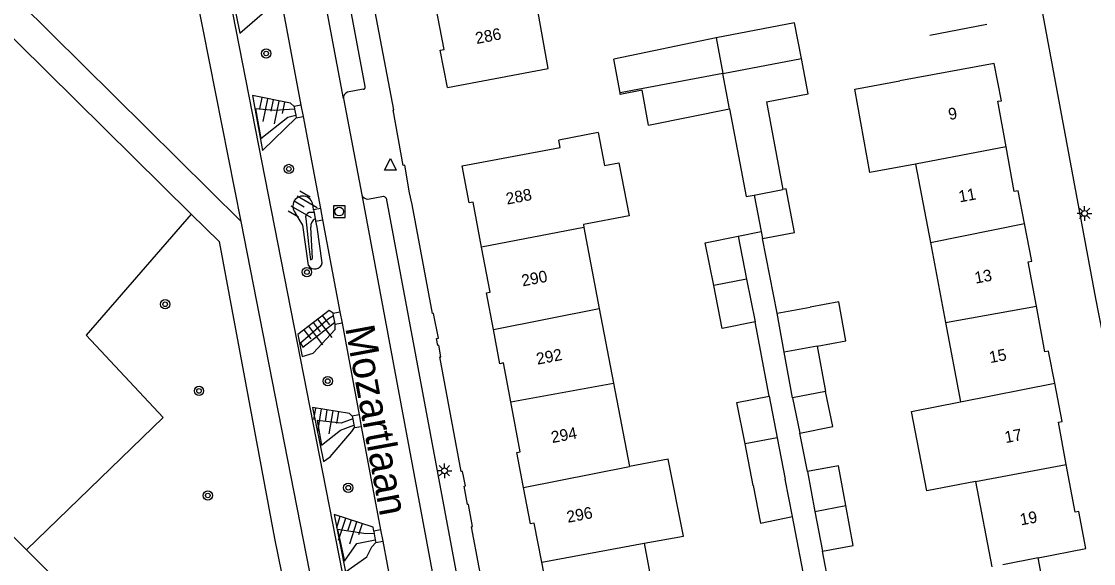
# Model space of a CAD drawing. Extents: x 132999 to 136000, y 398499 to 400501.
# Drawn here: x 133335 to 133427, y 398911.3 to 398957.8 of the extents above; entities that cross this region are included whole.
import ezdxf

# ---------------------------------------------------------------- set-up
doc = ezdxf.new("R2010")
doc.units = 0
for name, color, linetype in [('gg-afsc-erfafscheiding', 7, 'Continuous'), ('gg-afsc-hekwerk', 7, 'Continuous'), ('gg-afsc-muur', 7, 'Continuous'), ('gg-anno-huisnummerreeks BGT', 7, 'Continuous'), ('gg-anno-openbare ruimte label', 7, 'Continuous'), ('gg-bbg-bijgebouw', 7, 'Continuous'), ('gg-bbg-gedigitaliseerde bebouwing', 7, 'Continuous'), ('gg-bbg-gedigitaliseerde bijgebouw', 7, 'Continuous'), ('gg-bbg-hoofdgebouw', 7, 'Continuous'), ('gg-bbg-luifel en loopbrug', 7, 'Continuous'), ('gg-bbg-tussenscheiding', 7, 'Continuous'), ('gg-knt-bovenkant onderkant talud', 7, 'Continuous'), ('gg-knt-verharding', 7, 'Continuous'), ('gg-knt-verharding nz', 7, 'Continuous'), ('gt-grn-groengrens', 7, 'Continuous'), ('gt-symb-boom', 7, 'Continuous'), ('gt-symb-lichtmast', 7, 'Continuous'), ('gt-symb-rioolschacht', 7, 'Continuous'), ('gt-symb-talud symbool', 7, 'Continuous'), ('gt-symb-waterafsluiter', 7, 'Continuous')]:
    doc.layers.add(name, color=color, linetype=linetype)

# ---------------------------------------------------------------- blocks, each defined once
blk = doc.blocks.new('gt0-WAFSL')
at = {"layer": 'gt-symb-waterafsluiter'}
for p, q in [((-0.5, -0.333), (0, 0.667)), ((0, 0.667), (0.5, -0.333)), ((0.5, -0.333), (-0.5, -0.333))]:
    blk.add_line(p, q, dxfattribs=at)
blk = doc.blocks.new('gt0-TALUD_1')
at = {"layer": 'gt-symb-talud symbool'}
for p, q in [((-1, -1), (-1, 0)), ((-0.5, -2), (-0.5, 0)), ((0, -1), (0, 0)), ((0.5, -2), (0.5, 0)), ((1, -1), (1, 0))]:
    blk.add_line(p, q, dxfattribs=at)
blk = doc.blocks.new('gt0-BOOM')
at = {"layer": 'gt-symb-boom'}
for radius in [0.4, 0.2]:
    blk.add_circle((0, 0), radius, dxfattribs=at)
blk = doc.blocks.new('gt0-LMAST')
at = {"layer": 'gt-symb-lichtmast'}
for p, q in [((-0.182, 0.173), (-0.447, 0.438)), ((-0.005, 0.246), (-0.005, 0.621)), ((0.172, 0.173), (0.437, 0.438)), ((-0.255, -0.004), (-0.63, -0.004)), ((-0.182, -0.181), (-0.447, -0.446)), ((-0.005, -0.254), (-0.005, -0.629)), ((0.437, -0.446), (0.172, -0.181)), ((0.245, -0.004), (0.62, -0.004))]:
    blk.add_line(p, q, dxfattribs=at)
blk.add_circle((-0.005, -0.004), 0.25, dxfattribs=at)
blk = doc.blocks.new('gt0-RS')
at = {"layer": 'gt-symb-rioolschacht'}
blk.add_lwpolyline([(-0.5, -0.5), (0.5, -0.5), (0.5, 0.5), (-0.5, 0.5)], close=True, dxfattribs=at)
blk.add_circle((0, 0), 0.375, dxfattribs=at)

msp = doc.modelspace()

# ---------------------------------------------------------------- linework, layer by layer
at = {"layer": 'gg-afsc-erfafscheiding'}
for p, q in [((133396.506, 398939.394), (133398.476, 398939.786)), ((133399.86, 398932.801), (133398.591, 398939.185)), ((133399.171, 398925.662), (133397.972, 398932.036)), ((133402.473, 398919.203), (133401.804, 398922.492)), ((133402.409, 398908.948), (133401.17, 398915.344)), ((133404.553, 398908.312), (133403.743, 398912.387))]:
    msp.add_line(p, q, dxfattribs=at)
at = {"layer": 'gg-afsc-hekwerk'}
msp.add_line((133368.467, 398880.359), (133351.55, 398966.66), dxfattribs=at)
at = {"layer": 'gg-afsc-muur'}
msp.add_line((133417.869, 398957.553), (133412.961, 398956.596), dxfattribs=at)
at = {"layer": 'gg-bbg-bijgebouw'}
for p, q in [((133386.375, 398951.675), (133385.828, 398954.576)), ((133423.41, 398905.91), (133422.26, 398911.81))]:
    msp.add_line(p, q, dxfattribs=at)
msp.add_lwpolyline([(133388.828, 398948.905), (133388.262, 398951.908), (133386.397, 398951.557), (133386.375, 398951.675)], dxfattribs=at)
at = {"layer": 'gg-bbg-gedigitaliseerde bebouwing'}
for p, q in [((133380.216, 398953.787), (133378.938, 398960.85)), ((133418.48, 398954.19), (133410.389, 398952.71)), ((133411.744, 398945.564), (133413.015, 398938.858)), ((133383.222, 398940.391), (133383.272, 398940.127)), ((133383.272, 398940.127), (133384.594, 398933.194)), ((133413.015, 398938.858), (133414.318, 398931.984)), ((133384.594, 398933.194), (133385.815, 398926.786)), ((133414.318, 398931.984), (133415.605, 398925.194)), ((133385.815, 398926.786), (133387.18, 398919.63)), ((133416.899, 398918.366), (133418.291, 398911.026)), ((133388.431, 398913.064), (133389.842, 398905.663))]:
    msp.add_line(p, q, dxfattribs=at)
for points in [[(133411.744, 398945.564), (133407.83, 398944.848), (133406.521, 398952.003), (133410.389, 398952.71)], [(133384.488, 398948.286), (133385.027, 398945.456), (133386.278, 398945.694), (133387.147, 398941.14), (133383.222, 398940.391)], [(133416.899, 398918.366), (133412.72, 398917.548), (133411.385, 398924.368), (133415.605, 398925.194)], [(133388.431, 398913.064), (133391.808, 398913.681), (133390.516, 398920.283), (133387.18, 398919.63)]]:
    msp.add_lwpolyline(points, dxfattribs=at)
at = {"layer": 'gg-bbg-gedigitaliseerde bijgebouw'}
for p, q in [((133394.628, 398956.397), (133385.828, 398954.576)), ((133398.959, 398950.913), (133400.336, 398943.385)), ((133388.828, 398948.905), (133395.784, 398950.31)), ((133397.879, 398942.916), (133398.476, 398939.786)), ((133398.476, 398939.786), (133398.591, 398939.185)), ((133396.506, 398939.394), (133397.239, 398935.715)), ((133397.239, 398935.715), (133397.972, 398932.036)), ((133399.86, 398932.801), (133402.699, 398933.319)), ((133400.47, 398929.456), (133399.86, 398932.801)), ((133403.309, 398929.974), (133404.023, 398926.062)), ((133401.183, 398925.544), (133400.47, 398929.456)), ((133404.023, 398926.062), (133401.183, 398925.544)), ((133399.171, 398925.662), (133399.866, 398922.113)), ((133399.866, 398922.113), (133400.561, 398918.564)), ((133397.804, 398918.024), (133397.109, 398921.573)), ((133401.17, 398915.344), (133400.561, 398918.564)), ((133402.473, 398919.203), (133403.108, 398915.795)), ((133403.108, 398915.795), (133403.743, 398912.387))]:
    msp.add_line(p, q, dxfattribs=at)
for points in [[(133401.938, 398954.634), (133401.36, 398957.677), (133394.628, 398956.397)], [(133398.959, 398950.913), (133402.517, 398951.589), (133401.938, 398954.634)], [(133395.784, 398950.31), (133397.213, 398942.79), (133397.879, 398942.916)], [(133398.591, 398939.185), (133401.348, 398939.711), (133400.636, 398943.442), (133400.336, 398943.385)], [(133394.417, 398935.153), (133393.684, 398938.832), (133396.506, 398939.394)], [(133397.972, 398932.036), (133395.149, 398931.474), (133394.417, 398935.153)], [(133403.309, 398929.974), (133405.771, 398930.424), (133405.16, 398933.769), (133402.699, 398933.319)], [(133397.109, 398921.573), (133396.414, 398925.122), (133399.171, 398925.662)], [(133405.753, 398916.287), (133405.118, 398919.696), (133402.473, 398919.203)], [(133397.804, 398918.024), (133398.437, 398914.793), (133401.17, 398915.344)], [(133403.743, 398912.387), (133406.388, 398912.88), (133405.753, 398916.287)]]:
    msp.add_lwpolyline(points, dxfattribs=at)
at = {"layer": 'gg-bbg-hoofdgebouw'}
for p, q in [((133371.56, 398952.15), (133380.216, 398953.787)), ((133384.488, 398948.286), (133381.12, 398947.63))]:
    msp.add_line(p, q, dxfattribs=at)
for points in [[(133371.56, 398952.15), (133370.94, 398955.34), (133371.26, 398955.4), (133370.517, 398959.241)], [(133419.527, 398947.049), (133418.82, 398950.96), (133419.13, 398951.01), (133418.48, 398954.19)], [(133374.485, 398938.448), (133373.75, 398942.3), (133373.43, 398942.24), (133372.83, 398945.42), (133381.23, 398947), (133381.12, 398947.63)], [(133421.1, 398940.47), (133420.54, 398943.28), (133420.22, 398943.22), (133419.527, 398947.049)], [(133422.117, 398933.406), (133421.42, 398937.2), (133421.74, 398937.26), (133421.1, 398940.47)], [(133375.502, 398931.382), (133374.9, 398934.54), (133375.22, 398934.6), (133374.485, 398938.448)], [(133423.689, 398926.776), (133423.15, 398929.53), (133422.84, 398929.47), (133422.117, 398933.406)], [(133377.001, 398925.178), (133376.37, 398928.52), (133376.06, 398928.46), (133375.502, 398931.382)], [(133424.686, 398919.817), (133424.01, 398923.44), (133424.33, 398923.5), (133423.689, 398926.776)], [(133378.086, 398917.85), (133377.5, 398920.83), (133377.81, 398920.89), (133377.001, 398925.178)], [(133422.26, 398911.81), (133426.36, 398912.62), (133425.77, 398915.77), (133425.45, 398915.72), (133424.686, 398919.817)], [(133379.656, 398911.429), (133379.01, 398914.79), (133378.7, 398914.73), (133378.086, 398917.85)], [(133384.83, 398904.68), (133380.75, 398903.88), (133380.16, 398907.08), (133380.48, 398907.14), (133379.656, 398911.429)]]:
    msp.add_lwpolyline(points, dxfattribs=at)
at = {"layer": 'gg-bbg-luifel en loopbrug'}
msp.add_line((133401.183, 398925.544), (133401.804, 398922.492), dxfattribs=at)
msp.add_lwpolyline([(133401.804, 398922.492), (133404.632, 398923.068), (133404.023, 398926.062)], dxfattribs=at)
at = {"layer": 'gg-bbg-tussenscheiding'}
for p, q in [((133394.628, 398956.397), (133395.206, 398953.354)), ((133395.206, 398953.354), (133401.938, 398954.634)), ((133395.206, 398953.354), (133386.375, 398951.675)), ((133395.784, 398950.31), (133395.206, 398953.354)), ((133419.527, 398947.049), (133411.744, 398945.564)), ((133397.879, 398942.916), (133400.336, 398943.385)), ((133383.272, 398940.127), (133374.485, 398938.448)), ((133413.015, 398938.858), (133421.1, 398940.47)), ((133397.239, 398935.715), (133394.417, 398935.153)), ((133375.502, 398931.382), (133384.594, 398933.194)), ((133414.318, 398931.984), (133422.117, 398933.406)), ((133403.309, 398929.974), (133400.47, 398929.456)), ((133377.001, 398925.178), (133385.815, 398926.786)), ((133415.605, 398925.194), (133423.689, 398926.776)), ((133399.866, 398922.113), (133397.109, 398921.573)), ((133378.086, 398917.85), (133387.18, 398919.63)), ((133416.899, 398918.366), (133424.686, 398919.817)), ((133403.108, 398915.795), (133405.753, 398916.287)), ((133379.656, 398911.429), (133388.431, 398913.064)), ((133422.26, 398911.81), (133419.241, 398911.214))]:
    msp.add_line(p, q, dxfattribs=at)
at = {"layer": 'gg-knt-bovenkant onderkant talud'}
for p, q in [((133360.065, 398941.667), (133360.015, 398941.932)), ((133360.112, 398941.417), (133359.671, 398941.412))]:
    msp.add_line(p, q, dxfattribs=at)
for points in [[(133356.529, 398960.361), (133356.488, 398960.655), (133352.773, 398961.473), (133353.723, 398956.813), (133356.714, 398959.378)], [(133358.39, 398950.522), (133358.093, 398950.787), (133354.81, 398951.451), (133355.667, 398946.754), (133358.576, 398949.539)], [(133358.436, 398950.278), (133356.715, 398950.16), (133355.071, 398950.313), (133355.53, 398947.782), (133357.841, 398949.605), (133358.534, 398949.762)], [(133359.622, 398936.876), (133359.14, 398940.33), (133358.519, 398941.361)], [(133359.395, 398940.904), (133359.616, 398938.749), (133359.803, 398937.365), (133359.974, 398937.476), (133359.82, 398940.176)], [(133360.804, 398937.095), (133360.383, 398940.176), (133360.251, 398940.684)], [(133361.736, 398932.8), (133361.415, 398933.03), (133358.711, 398930.965), (133359.091, 398929.063), (133360.041, 398929.349), (133361.917, 398931.405), (133361.921, 398931.818)], [(133361.778, 398932.574), (133361.355, 398932.31), (133358.947, 398930.214), (133359.149, 398929.881), (133360.403, 398930.842), (133361.882, 398932.023)], [(133363.388, 398923.957), (133363.135, 398924.181), (133359.971, 398924.705), (133360.91, 398920.079), (133361.499, 398920.465), (133363.336, 398922.633), (133363.571, 398922.974)], [(133363.428, 398923.742), (133362.431, 398923.361), (133360.357, 398923.593), (133360.73, 398921.484), (133362.383, 398922.764), (133363.531, 398923.187)], [(133365.227, 398914.102), (133365.185, 398914.454), (133361.837, 398915.539), (133362.801, 398910.617), (133364.625, 398911.883), (133365.076, 398912.752), (133365.411, 398913.119)], [(133365.271, 398913.865), (133364.372, 398913.884), (133362.125, 398914.233), (133362.728, 398911.537), (133363.783, 398913.027), (133365.364, 398913.367)]]:
    msp.add_lwpolyline(points, dxfattribs=at)
for centre, radius, start, end in [((133359.147, 398941.961), 0.868, 358.10964, 223.67252), ((133359.793, 398941.017), 0.414, 107.16902, 195.79989), ((133360.587, 398940.219), 0.769, 119.23844, 183.22626), ((133360.168, 398937.231), 0.651, 213.02758, 347.96579)]:
    msp.add_arc(centre, radius, start, end, dxfattribs=at)
at = {"layer": 'gg-knt-verharding'}
for p, q in [((133364.487, 398952.226), (133360.138, 398975.507)), ((133357.304, 398959.49), (133358.979, 398950.633)), ((133364.329, 398951.993), (133362.986, 398951.73)), ((133362.631, 398951.207), (133364.206, 398942.927)), ((133358.979, 398950.633), (133358.39, 398950.522)), ((133358.39, 398950.522), (133358.436, 398950.278)), ((133358.436, 398950.278), (133358.534, 398949.762)), ((133358.534, 398949.762), (133358.576, 398949.539)), ((133358.979, 398950.633), (133359.165, 398949.651)), ((133358.576, 398949.539), (133359.165, 398949.651)), ((133359.165, 398949.651), (133360.655, 398941.778)), ((133360.655, 398941.778), (133360.065, 398941.667)), ((133360.065, 398941.667), (133360.112, 398941.417)), ((133360.655, 398941.778), (133360.84, 398940.795)), ((133360.112, 398941.417), (133360.212, 398940.89)), ((133360.212, 398940.89), (133360.251, 398940.684)), ((133360.251, 398940.684), (133360.84, 398940.795)), ((133360.84, 398940.795), (133362.325, 398932.911)), ((133361.736, 398932.8), (133362.325, 398932.911)), ((133361.778, 398932.574), (133361.736, 398932.8)), ((133361.882, 398932.023), (133361.778, 398932.574)), ((133362.325, 398932.911), (133362.511, 398931.929)), ((133361.921, 398931.818), (133361.882, 398932.023)), ((133362.511, 398931.929), (133361.921, 398931.818)), ((133362.511, 398931.929), (133363.978, 398924.068)), ((133363.978, 398924.068), (133363.388, 398923.957)), ((133363.388, 398923.957), (133363.428, 398923.742)), ((133363.978, 398924.068), (133364.161, 398923.084)), ((133363.428, 398923.742), (133363.531, 398923.187)), ((133363.531, 398923.187), (133363.571, 398922.974)), ((133363.571, 398922.974), (133364.161, 398923.084)), ((133364.161, 398923.084), (133365.817, 398914.212)), ((133365.817, 398914.212), (133365.227, 398914.102)), ((133365.227, 398914.102), (133365.271, 398913.865)), ((133365.271, 398913.865), (133365.364, 398913.367)), ((133365.817, 398914.212), (133366.001, 398913.229)), ((133365.364, 398913.367), (133365.411, 398913.119)), ((133365.411, 398913.119), (133366.001, 398913.229)), ((133366.001, 398913.229), (133367.652, 398904.383))]:
    msp.add_line(p, q, dxfattribs=at)
for points in [[(133420.919, 398967.55), (133422.677, 398958.356), (133427.204, 398934.047), (133428.999, 398924.875), (133429.846, 398920.45)], [(133376.91, 398897.02), (133373.625, 398914.476), (133373.702, 398914.498), (133373.355, 398916.391), (133373.271, 398916.386), (133372.983, 398917.965), (133373.101, 398917.986), (133372.862, 398919.228), (133372.746, 398919.214), (133370.907, 398929.039), (133371, 398929.055), (133370.817, 398930.043), (133370.719, 398930.029), (133370.614, 398930.612), (133370.783, 398930.658), (133370.371, 398932.775), (133370.281, 398932.76), (133368.523, 398942.118), (133368.297, 398943.107), (133367.883, 398945.475), (133367.764, 398945.459), (133366.883, 398950.223), (133366.946, 398950.238), (133364.536, 398962.859)], [(133364.734, 398942.582), (133366.053, 398942.828), (133366.186, 398942.768), (133366.285, 398942.656), (133373.853, 398902.293)]]:
    msp.add_lwpolyline(points, dxfattribs=at)
for centre, radius, start, end in [((133363.092, 398951.276), 0.466, 103.12938, 188.53516), ((133364.32, 398952.169), 0.177, 273.04752, 18.66918), ((133364.714, 398943.128), 0.546, 201.56961, 272.10845)]:
    msp.add_arc(centre, radius, start, end, dxfattribs=at)
at = {"layer": 'gg-knt-verharding nz'}
for p, q in [((133362.631, 398951.207), (133358.037, 398975.789)), ((133364.206, 398942.927), (133372.004, 398901.291))]:
    msp.add_line(p, q, dxfattribs=at)
at = {"layer": 'gt-grn-groengrens'}
for p, q in [((133353.832, 398940.649), (133348.293, 398968.817)), ((133335.419, 398912.504), (133293.178, 398954.571))]:
    msp.add_line(p, q, dxfattribs=at)
for points in [[(133349.553, 398941.293), (133332.176, 398958.394), (133314.577, 398976.112)], [(133353.832, 398940.649), (133332.079, 398962.182), (133331.254, 398963.134)], [(133349.553, 398941.293), (133351.96, 398938.924), (133356.71, 398913.481), (133361.332, 398890.752), (133360.579, 398888.993), (133359.853, 398888.643), (133346.817, 398901.153), (133335.419, 398912.504)], [(133349.553, 398941.293), (133340.549, 398930.907), (133347.151, 398923.853), (133335.419, 398912.504)], [(133364.429, 398878.903), (133364.493, 398879.138), (133364.437, 398883.557), (133363.948, 398887.484), (133361.066, 398903.862), (133353.832, 398940.649)]]:
    msp.add_lwpolyline(points, dxfattribs=at)

# ---------------------------------------------------------------- block references
at = {"layer": 'gt-symb-boom'}
for p in [(133355.992, 398955.059), (133357.938, 398945.156), (133359.492, 398936.314), (133347.322, 398933.557), (133361.279, 398926.971), (133350.226, 398926.122), (133350.985, 398917.156)]:
    msp.add_blockref('gt0-BOOM', p, dxfattribs=at)
at = {"layer": 'gt-symb-boom', "rotation": -79.10581701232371}
msp.add_blockref('gt0-BOOM', (133363.041, 398917.82), dxfattribs=at)
at = {"layer": 'gt-symb-lichtmast'}
for p in [(133426.263, 398941.352), (133371.305, 398919.278)]:
    msp.add_blockref('gt0-LMAST', p, dxfattribs=at)
at = {"layer": 'gt-symb-rioolschacht'}
msp.add_blockref('gt0-RS', (133362.267, 398941.504), dxfattribs=at)
at = {"layer": 'gt-symb-talud symbool'}
for p, xscale, yscale, rotation in [((133356.624, 398951.084), 0.9998019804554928, 0.9998019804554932, -11.422321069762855), ((133358.393, 398942.39), 1.0001144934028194, 1.0001144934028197, 59.87139976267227), ((133360.043, 398931.982), 1.00023697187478, 1.0002369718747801, 37.36253068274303), ((133361.24, 398924.495), 1.0005323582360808, 1.000532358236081, -9.434079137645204), ((133363.307, 398915.063), 0.9996324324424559, 0.9996324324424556, -17.9455630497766)]:
    msp.add_blockref('gt0-TALUD_1', p, dxfattribs=dict(at, xscale=xscale, yscale=yscale, rotation=rotation))
at = {"layer": 'gt-symb-waterafsluiter'}
msp.add_blockref('gt0-WAFSL', (133366.657, 398945.4), dxfattribs=at)

# ---------------------------------------------------------------- texts
at = {"layer": 'gg-anno-huisnummerreeks BGT'}
for s, rotation, p in [('286', 11, (133374.057, 398955.866)), ('9', 10.3, (133414.652, 398949.347)), ('288', 10.8, (133376.675, 398942.097)), ('11', 10.3, (133415.535, 398942.288)), ('290', 10.8, (133378.014, 398935.081)), ('13', 10.4, (133416.908, 398935.324)), ('292', 10.7, (133379.283, 398928.372)), ('15', 10.4, (133418.16, 398928.506)), ('294', 10.7, (133380.551, 398921.647)), ('17', 10.5, (133419.486, 398921.645)), ('296', 10.9, (133381.893, 398914.808)), ('19', 10.5, (133420.802, 398914.588))]:
    msp.add_text(s, height=1, rotation=rotation, dxfattribs=at).set_placement(p)
at = {"layer": 'gg-anno-openbare ruimte label'}
msp.add_text('Mozartlaan', height=2.5, rotation=280.5, dxfattribs=at).set_placement((133362.772, 398931.547))

doc.saveas('drawing.dxf')
